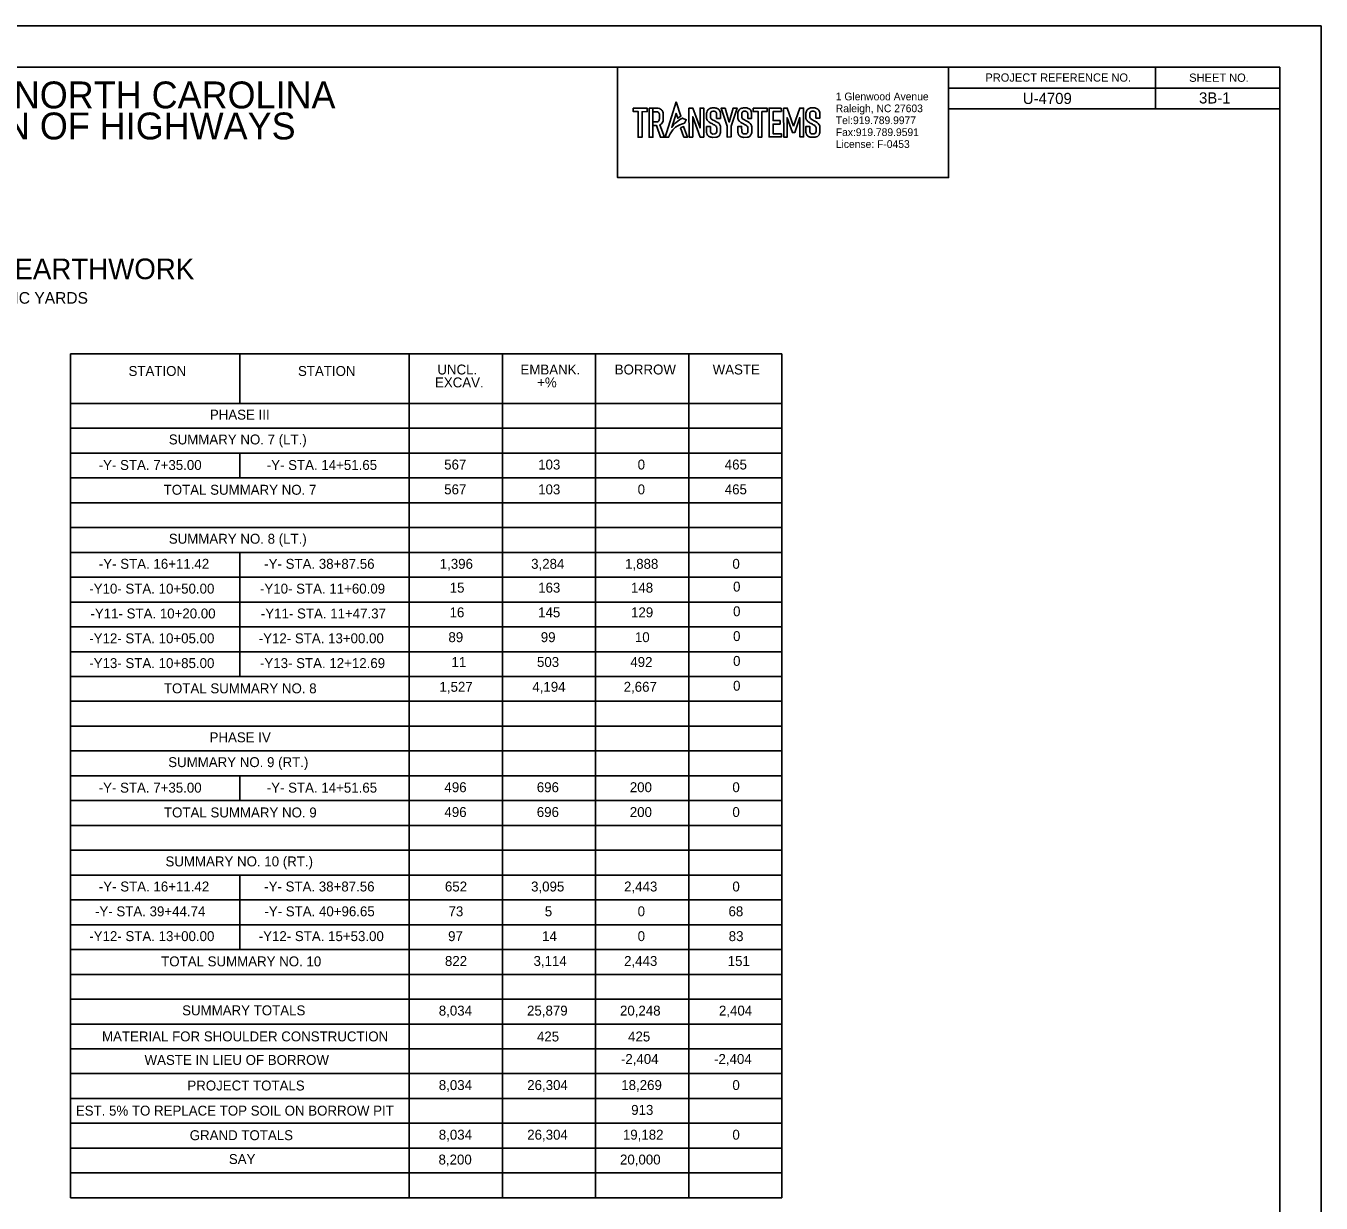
# Model space of a CAD drawing. Extents: x 573680 to 575380, y -53324 to -52224.
# Drawn here: x 574597 to 575380, y -52936 to -52224 of the extents above; entities that cross this region are included whole.
import ezdxf

# ---------------------------------------------------------------- set-up
doc = ezdxf.new("R2010")
doc.units = 0
for name, color, linetype in [('Old_Level_1', 7, 'Continuous'), ('Old_Level_2', 7, 'Continuous'), ('Old_Level_58', 7, 'Continuous'), ('Sheet Data Field CELL', 7, 'Continuous'), ('Sheet Plan And Profile CELL', 7, 'Continuous'), ('Sheet Plot Border Outside CELL', 7, 'Continuous'), ('Sheet Summary Combination CELL', 7, 'Continuous'), ('Sheet Summary Combination Grid CELL', 7, 'Continuous')]:
    doc.layers.add(name, color=color, linetype=linetype)

msp = doc.modelspace()

# ---------------------------------------------------------------- linework, layer by layer
at = {"layer": 'Old_Level_1'}
for points in [[(574990.11, -52270.23), (574983.45, -52291.56), (574985.67, -52291.55), (574986.01, -52290.71), (574986.59, -52289.55), (574986.9, -52288.92), (574987.27, -52288.39), (574987.8, -52287.63), (574988.12, -52287.16), (574988.5, -52286.77), (574988.88, -52286.37), (574989.37, -52285.88), (574989.78, -52285.61), (574990.2, -52285.27), (574990.75, -52284.95), (574991.25, -52284.67), (574992.46, -52284.1), (574993.46, -52283.69), (574995.11, -52283.13), (574996.24, -52280.99), (574994.07, -52280.04), (574992.43, -52280.92), (574991.06, -52281.83), (574990.08, -52282.62), (574989.55, -52283.05), (574989.02, -52283.62), (574988.48, -52284.18), (574988.08, -52284.61), (574987.71, -52285.26), (574987.5, -52285.62), (574990.13, -52277.24), (574991.12, -52280.13), (574993.02, -52278.87)], [(574964.15, -52274.08), (574972.62, -52274.07), (574972.62, -52276.14), (574969.51, -52276.15), (574969.52, -52291.57), (574967.17, -52291.57), (574967.16, -52276.04), (574964.19, -52276.05)], [(574973.77, -52274.08), (574976.09, -52274.08), (574976.1, -52291.64), (574973.79, -52291.65)], [(574976.09, -52276.16), (574978.48, -52276.16), (574978.78, -52276.21), (574979.18, -52276.38), (574979.5, -52276.59), (574979.74, -52276.87), (574979.89, -52277.2), (574980.01, -52277.45), (574980.01, -52278.03), (574980.02, -52280.52), (574979.96, -52280.85), (574979.88, -52281.3), (574979.75, -52281.59), (574979.55, -52281.85), (574979.28, -52282.07), (574978.85, -52282.22), (574978.53, -52282.26), (574978.2, -52282.3), (574976.09, -52282.31), (574976.1, -52284.42), (574978.21, -52284.41), (574980.58, -52291.57), (574983, -52291.55), (574980.35, -52284.01), (574980.73, -52283.87), (574981.26, -52283.47), (574981.75, -52282.94), (574982.1, -52282.31), (574982.31, -52281.67), (574982.3, -52281.49), (574982.34, -52276.92), (574982.14, -52276.18), (574981.77, -52275.5), (574981.36, -52275.03), (574980.66, -52274.55), (574979.99, -52274.33), (574979.31, -52274.1), (574978.9, -52274.1), (574976.09, -52274.08)], [(574997.88, -52274.04), (574997.9, -52291.5), (575000.13, -52291.5), (575000.12, -52279.22), (575004.58, -52291.53), (575006.83, -52291.5), (575006.8, -52273.99), (575004.63, -52274), (575004.64, -52285.98), (575000.24, -52274.04)], [(575014.58, -52280.22), (575016.89, -52280.21), (575016.89, -52276.74), (575016.69, -52276.03), (575016.41, -52275.44), (575016.11, -52275.05), (575015.74, -52274.7), (575015.3, -52274.42), (575014.88, -52274.24), (575014.88, -52274.24), (575014.42, -52274.05), (575013.94, -52273.93), (575013.62, -52273.85), (575011.87, -52273.88), (575011.34, -52273.97), (575010.88, -52274.05), (575010.42, -52274.29), (575010.01, -52274.5), (575009.62, -52274.79), (575009.31, -52275.1), (575009.07, -52275.47), (575008.87, -52275.86), (575008.62, -52276.56), (575008.57, -52277.07), (575008.57, -52280.24), (575008.68, -52280.72), (575008.91, -52281.21), (575009.2, -52281.62), (575009.5, -52281.93), (575009.95, -52282.28), (575010.4, -52282.63), (575010.69, -52282.85), (575011.17, -52283.07), (575011.65, -52283.3), (575012.04, -52283.55), (575012.48, -52283.84), (575013.01, -52284.11), (575013.44, -52284.32), (575013.87, -52284.64), (575014.18, -52284.93), (575014.43, -52285.17), (575014.59, -52285.65), (575014.68, -52285.95), (575014.65, -52288.19), (575014.49, -52288.67), (575014.24, -52289.09), (575013.91, -52289.38), (575013.56, -52289.54), (575013.22, -52289.62), (575012.25, -52289.64), (575011.93, -52289.55), (575011.6, -52289.35), (575011.27, -52289.16), (575011.13, -52288.82), (575010.99, -52288.49), (575010.88, -52288.22), (575010.84, -52285.11), (575008.5, -52285.14), (575008.55, -52288.85), (575008.66, -52289.13), (575008.93, -52289.99), (575009.11, -52290.28), (575009.36, -52290.6), (575009.74, -52290.98), (575010.05, -52291.17), (575010.48, -52291.35), (575010.64, -52291.42), (575011.07, -52291.6), (575011.6, -52291.65), (575012, -52291.69), (575014.14, -52291.64), (575014.73, -52291.5), (575015.56, -52291.12), (575015.84, -52291), (575016.46, -52290.21), (575016.79, -52289.42), (575016.95, -52288.71), (575016.9, -52285.29), (575016.89, -52284.81), (575016.76, -52284.44), (575016.57, -52284.08), (575016.03, -52283.33), (575015.32, -52282.77), (575014.34, -52282.19), (575013.6, -52281.75), (575012.14, -52280.98), (575011.38, -52280.42), (575011.05, -52280), (575010.98, -52279.71), (575010.9, -52279.43), (575010.94, -52277), (575011.07, -52276.74), (575011.19, -52276.49), (575011.37, -52276.33), (575011.6, -52276.14), (575011.86, -52276.03), (575012.12, -52275.92), (575012.27, -52275.95), (575012.28, -52275.88), (575013.24, -52275.89), (575013.52, -52276), (575013.79, -52276.11), (575014.07, -52276.22), (575014.2, -52276.42), (575014.39, -52276.69), (575014.48, -52276.97), (575014.57, -52277.25), (575014.56, -52277.55)], [(575019.85, -52274.03), (575017.31, -52274.04), (575020.93, -52284.92), (575020.96, -52291.46), (575023.35, -52291.45), (575023.32, -52284.96), (575026.98, -52273.99), (575024.49, -52274.06), (575022.18, -52282.4)], [(575033.45, -52280.2), (575035.76, -52280.2), (575035.76, -52276.72), (575035.56, -52276.01), (575035.28, -52275.42), (575034.98, -52275.03), (575034.61, -52274.68), (575034.17, -52274.4), (575033.75, -52274.22), (575033.75, -52274.22), (575033.29, -52274.03), (575032.81, -52273.91), (575032.49, -52273.83), (575030.74, -52273.87), (575030.21, -52273.96), (575029.75, -52274.04), (575029.29, -52274.28), (575028.89, -52274.49), (575028.49, -52274.77), (575028.18, -52275.08), (575027.94, -52275.45), (575027.74, -52275.84), (575027.49, -52276.54), (575027.44, -52277.06), (575027.44, -52280.23), (575027.56, -52280.7), (575027.78, -52281.2), (575028.07, -52281.61), (575028.37, -52281.92), (575028.82, -52282.26), (575029.27, -52282.61), (575029.56, -52282.83), (575030.04, -52283.06), (575030.52, -52283.28), (575030.91, -52283.53), (575031.36, -52283.82), (575031.88, -52284.09), (575032.32, -52284.31), (575032.75, -52284.62), (575033.06, -52284.92), (575033.31, -52285.15), (575033.46, -52285.64), (575033.55, -52285.93), (575033.52, -52288.17), (575033.36, -52288.65), (575033.11, -52289.07), (575032.78, -52289.37), (575032.43, -52289.53), (575032.09, -52289.6), (575031.13, -52289.62), (575030.8, -52289.53), (575030.48, -52289.33), (575030.15, -52289.14), (575030, -52288.81), (575029.86, -52288.47), (575029.75, -52288.2), (575029.71, -52285.09), (575027.37, -52285.12), (575027.42, -52288.83), (575027.54, -52289.11), (575027.81, -52289.97), (575027.98, -52290.27), (575028.23, -52290.58), (575028.61, -52290.96), (575028.92, -52291.15), (575029.35, -52291.33), (575029.51, -52291.4), (575029.94, -52291.58), (575030.48, -52291.64), (575030.87, -52291.67), (575033.01, -52291.62), (575033.6, -52291.48), (575034.43, -52291.11), (575034.71, -52290.98), (575035.33, -52290.19), (575035.67, -52289.4), (575035.82, -52288.69), (575035.77, -52285.27), (575035.76, -52284.8), (575035.63, -52284.42), (575035.44, -52284.07), (575034.9, -52283.31), (575034.19, -52282.75), (575033.22, -52282.17), (575032.47, -52281.73), (575031.01, -52280.96), (575030.25, -52280.4), (575029.93, -52279.98), (575029.85, -52279.69), (575029.77, -52279.41), (575029.82, -52276.98), (575029.94, -52276.72), (575030.06, -52276.47), (575030.24, -52276.32), (575030.47, -52276.12), (575030.73, -52276.01), (575030.99, -52275.91), (575031.14, -52275.94), (575031.15, -52275.86), (575032.11, -52275.88), (575032.39, -52275.99), (575032.67, -52276.1), (575032.94, -52276.21), (575033.07, -52276.4), (575033.26, -52276.68), (575033.35, -52276.95), (575033.44, -52277.23), (575033.44, -52277.53)], [(575036.61, -52274.01), (575045.08, -52274), (575045.08, -52276.08), (575041.97, -52276.08), (575041.98, -52291.5), (575039.63, -52291.5), (575039.62, -52275.98), (575036.65, -52275.98)], [(575053.68, -52274), (575046.3, -52274.01), (575046.31, -52291.44), (575053.78, -52291.43), (575053.78, -52289.46), (575048.74, -52289.46), (575048.73, -52283.62), (575052.95, -52283.62), (575052.95, -52281.54), (575048.69, -52281.54), (575048.69, -52276.05), (575053.7, -52276.04)], [(575061.06, -52284.85), (575057.25, -52273.93), (575055.03, -52274.04), (575055.12, -52291.5), (575057.23, -52291.49), (575057.17, -52279.81), (575060.44, -52288.8), (575061.79, -52288.83), (575064.85, -52279.7), (575064.9, -52291.42), (575067.18, -52291.41), (575067.11, -52273.99), (575064.81, -52274)], [(575074.58, -52280.16), (575076.9, -52280.16), (575076.89, -52276.68), (575076.7, -52275.98), (575076.42, -52275.39), (575076.12, -52275), (575075.75, -52274.64), (575075.31, -52274.36), (575074.88, -52274.19), (575074.88, -52274.19), (575074.42, -52273.99), (575073.94, -52273.87), (575073.62, -52273.79), (575071.87, -52273.83), (575071.34, -52273.92), (575070.88, -52274), (575070.42, -52274.24), (575070.02, -52274.45), (575069.62, -52274.73), (575069.31, -52275.05), (575069.07, -52275.41), (575068.88, -52275.81), (575068.62, -52276.5), (575068.57, -52277.02), (575068.57, -52280.19), (575068.69, -52280.66), (575068.92, -52281.16), (575069.21, -52281.57), (575069.5, -52281.88), (575069.95, -52282.23), (575070.41, -52282.57), (575070.69, -52282.79), (575071.17, -52283.02), (575071.66, -52283.24), (575072.05, -52283.5), (575072.49, -52283.78), (575073.02, -52284.05), (575073.45, -52284.27), (575073.88, -52284.58), (575074.19, -52284.88), (575074.44, -52285.12), (575074.59, -52285.6), (575074.69, -52285.9), (575074.65, -52288.13), (575074.49, -52288.62), (575074.24, -52289.04), (575073.92, -52289.33), (575073.56, -52289.49), (575073.22, -52289.56), (575072.26, -52289.58), (575071.94, -52289.49), (575071.61, -52289.3), (575071.28, -52289.1), (575071.14, -52288.77), (575070.99, -52288.43), (575070.88, -52288.17), (575070.84, -52285.05), (575068.51, -52285.08), (575068.55, -52288.79), (575068.67, -52289.07), (575068.94, -52289.93), (575069.11, -52290.23), (575069.37, -52290.55), (575069.75, -52290.92), (575070.05, -52291.11), (575070.49, -52291.3), (575070.64, -52291.36), (575071.07, -52291.54), (575071.61, -52291.6), (575072, -52291.64), (575074.14, -52291.58), (575074.74, -52291.44), (575075.56, -52291.07), (575075.84, -52290.94), (575076.46, -52290.15), (575076.8, -52289.36), (575076.95, -52288.65), (575076.9, -52285.23), (575076.89, -52284.76), (575076.76, -52284.38), (575076.57, -52284.03), (575076.03, -52283.27), (575075.32, -52282.71), (575074.35, -52282.13), (575073.6, -52281.69), (575072.14, -52280.92), (575071.39, -52280.36), (575071.06, -52279.94), (575070.98, -52279.66), (575070.9, -52279.37), (575070.95, -52276.94), (575071.07, -52276.69), (575071.2, -52276.43), (575071.37, -52276.28), (575071.61, -52276.08), (575071.86, -52275.98), (575072.12, -52275.87), (575072.27, -52275.9), (575072.29, -52275.82), (575073.24, -52275.84), (575073.52, -52275.95), (575073.8, -52276.06), (575074.08, -52276.17), (575074.21, -52276.36), (575074.39, -52276.64), (575074.48, -52276.91), (575074.58, -52277.19), (575074.57, -52277.5)], [(574992.73, -52285.93), (574994.64, -52285.17), (574996.91, -52291.61), (574994.81, -52291.53)]]:
    msp.add_lwpolyline(points, close=True, dxfattribs=at)
at = {"layer": 'Old_Level_58'}
msp.add_lwpolyline([(574954.76, -52249.31), (575154.81, -52249.31), (575154.81, -52316), (574954.76, -52316)], close=True, dxfattribs=at)
at = {"layer": 'Sheet Plan And Profile CELL'}
for points in [[(575354.86, -52249.31), (573854.86, -52249.31), (573854.86, -53299.31), (575354.86, -53299.31)], [(575154.81, -52249.31), (575354.86, -52249.31), (575354.86, -52274.36), (575154.81, -52274.36)]]:
    msp.add_lwpolyline(points, close=True, dxfattribs=at)
at = {"layer": 'Sheet Plot Border Outside CELL'}
msp.add_lwpolyline([(573679.86, -53324.31), (575379.86, -53324.31), (575379.86, -52224.31), (573679.86, -52224.31)], close=True, dxfattribs=at)
at = {"layer": 'Sheet Summary Combination CELL'}
for p, q in [((575279.86, -52249.36), (575279.86, -52274.36)), ((575154.81, -52261.86), (575354.86, -52261.86)), ((575154.81, -52274.36), (575354.86, -52274.36)), ((574773.7, -52422.43), (574773.7, -52422.43)), ((574755.34, -52422.55), (574755.34, -52422.55)), ((574762.84, -52422.67), (574762.84, -52422.67)), ((574780.42, -52422.55), (574780.42, -52422.55))]:
    msp.add_line(p, q, dxfattribs=at)
msp.add_lwpolyline([(575154.81, -52249.31), (575354.86, -52249.31), (575354.86, -52274.36), (575154.81, -52274.36)], close=True, dxfattribs=at)
at = {"layer": 'Sheet Summary Combination Grid CELL'}
for p, q in [((574624.12, -52422.49), (575054.02, -52422.49)), ((574624.12, -52422.49), (574624.12, -52932.49)), ((574726.54, -52422.49), (574726.54, -52452.49)), ((574828.9, -52422.49), (574828.9, -52662.49)), ((574885.18, -52422.49), (574885.18, -52662.49)), ((574941.46, -52422.49), (574941.46, -52662.49)), ((574997.74, -52422.49), (574997.74, -52662.49)), ((575054.02, -52422.49), (575054.02, -52932.49)), ((574624.12, -52452.49), (575054.02, -52452.49)), ((574624.12, -52467.49), (575054.02, -52467.49)), ((574624.12, -52482.49), (575054.02, -52482.49)), ((574726.54, -52482.49), (574726.54, -52497.49)), ((574624.12, -52497.49), (575054.02, -52497.49)), ((574624.12, -52512.49), (575054.02, -52512.49)), ((574624.12, -52527.49), (575054.02, -52527.49)), ((574624.12, -52542.49), (575054.02, -52542.49)), ((574726.54, -52542.49), (574726.54, -52617.49)), ((574624.12, -52557.49), (575054.02, -52557.49)), ((574624.12, -52572.49), (575054.02, -52572.49)), ((574624.12, -52587.49), (575054.02, -52587.49)), ((574624.12, -52602.49), (575054.02, -52602.49)), ((574624.12, -52617.49), (575054.02, -52617.49)), ((574624.12, -52632.49), (575054.02, -52632.49)), ((574624.12, -52647.49), (575054.02, -52647.49)), ((574624.12, -52662.49), (575054.02, -52662.49)), ((574828.9, -52662.49), (574828.9, -52932.49)), ((574885.18, -52662.49), (574885.18, -52932.49)), ((574941.46, -52662.49), (574941.46, -52932.49)), ((574997.74, -52662.49), (574997.74, -52932.49)), ((574624.12, -52677.49), (575054.02, -52677.49)), ((574726.54, -52677.49), (574726.54, -52692.49)), ((574624.12, -52692.49), (575054.02, -52692.49)), ((574624.12, -52707.49), (575054.02, -52707.49)), ((574624.12, -52722.49), (575054.02, -52722.49)), ((574624.12, -52737.49), (575054.02, -52737.49)), ((574726.54, -52737.49), (574726.54, -52782.49)), ((574624.12, -52752.49), (575054.02, -52752.49)), ((574624.12, -52767.49), (575054.02, -52767.49)), ((574624.12, -52782.49), (575054.02, -52782.49)), ((574624.12, -52797.49), (575054.02, -52797.49)), ((574624.12, -52812.49), (575054.02, -52812.49)), ((574624.12, -52827.49), (575054.02, -52827.49)), ((574624.12, -52842.49), (575054.02, -52842.49)), ((574624.12, -52857.49), (575054.02, -52857.49)), ((574624.12, -52872.49), (575054.02, -52872.49)), ((574624.12, -52887.49), (575054.02, -52887.49)), ((574624.12, -52902.49), (575054.02, -52902.49)), ((574624.12, -52917.49), (575054.02, -52917.49)), ((574624.12, -52932.49), (575054.02, -52932.49))]:
    msp.add_line(p, q, dxfattribs=at)

# ---------------------------------------------------------------- texts
at = {"layer": 'Old_Level_2'}
for s, p in [('1 Glenwood Avenue', (575086.61, -52269.28)), ('Raleigh, NC 27603', (575086.61, -52276.47)), ('Tel:919.789.9977 ', (575086.61, -52283.67)), ('Fax:919.789.9591', (575086.61, -52290.87)), ('License: F-0453', (575086.61, -52298.06))]:
    msp.add_text(s, height=4.6576, rotation=360, dxfattribs=at).set_placement(p)
at = {"layer": 'Sheet Data Field CELL'}
for s, p in [('U-4709', (575199.61, -52271.51)), ('3B-1', (575306.08, -52271.21))]:
    msp.add_text(s, height=6.75, dxfattribs=at).set_placement(p)
at = {"layer": 'Sheet Plan And Profile CELL'}
for s, height, p in [('PROJECT REFERENCE NO.', 5.0001, (575177.01, -52258.01)), ('SHEET NO.', 5, (575300.16, -52258.11))]:
    msp.add_text(s, height=height, rotation=360, dxfattribs=at).set_placement(p)
at = {"layer": 'Sheet Summary Combination CELL'}
for s, height, p in [('STATE OF NORTH CAROLINA', 16.2501, (574477.61, -52274.16)), ('PROJECT REFERENCE NO.', 5.0001, (575177.01, -52258.01)), ('SHEET NO.', 5, (575300.16, -52258.11)), ('DIVISION OF HIGHWAYS', 16.2501, (574504.21, -52292.91)), ('STATION', 6, (574659.22, -52435.85)), ('STATION', 6, (574761.61, -52435.85)), ('UNCL.', 6, (574845.85, -52434.97)), ('EMBANK.', 6, (574896.06, -52434.97)), ('BORROW', 6, (574953.01, -52434.97)), ('WASTE', 6, (575012.21, -52434.97)), ('EXCAV.', 6, (574844.41, -52442.77)), ('+%', 6, (574906.14, -52442.77)), ('PHASE III', 6, (574708.38, -52462.24)), ('SUMMARY NO. 7 (LT.)', 6, (574683.55, -52477.24)), ('-Y- STA. 7+35.00', 6, (574641.18, -52492.66)), ('-Y- STA. 14+51.65', 6, (574742.75, -52492.66)), ('567', 6, (574849.96, -52492.4)), ('103', 6, (574906.76, -52492.4)), ('0', 6, (574966.87, -52492.4)), ('465', 6, (575019.51, -52492.4)), ('TOTAL SUMMARY NO. 7', 6, (574680.45, -52507.65)), ('567', 6, (574849.96, -52507.4)), ('103', 6, (574906.76, -52507.4)), ('0', 6, (574966.87, -52507.4)), ('465', 6, (575019.51, -52507.4)), ('SUMMARY NO. 8 (LT.)', 6, (574683.55, -52537.24)), ('-Y- STA. 16+11.42', 6, (574641.29, -52552.4)), ('-Y- STA. 38+87.56', 6, (574741.22, -52552.4)), ('1,396', 6, (574847.27, -52552.4)), ('3,284', 6, (574902.51, -52552.4)), ('1,888', 6, (574959.29, -52552.4)), ('0', 6, (575024.13, -52552.4)), ('-Y10- STA. 10+50.00', 6, (574635.5, -52567.4)), ('-Y10- STA. 11+60.09', 6, (574738.66, -52567.4)), ('15', 6, (574853.31, -52566.8)), ('163', 6, (574906.76, -52566.8)), ('148', 6, (574962.84, -52566.8)), ('0', 6, (575024.53, -52566.17)), ('-Y11- STA. 10+20.00', 6, (574636.22, -52582.4)), ('-Y11- STA. 11+47.37', 6, (574739.19, -52582.4)), ('16', 6, (574853.21, -52581.72)), ('145', 6, (574906.74, -52581.72)), ('129', 6, (574962.89, -52581.72)), ('0', 6, (575024.53, -52581.08)), ('-Y12- STA. 10+05.00', 6, (574635.5, -52597.4)), ('-Y12- STA. 13+00.00', 6, (574737.89, -52597.4)), ('89', 6, (574852.52, -52596.72)), ('99', 6, (574908.33, -52596.72)), ('10', 6, (574965.21, -52596.72)), ('0', 6, (575024.53, -52596.08)), ('-Y13- STA. 10+85.00', 6, (574635.5, -52612.4)), ('-Y13- STA. 12+12.69', 6, (574738.66, -52612.4)), ('11', 6, (574854.37, -52611.72)), ('503', 6, (574906.04, -52611.72)), ('492', 6, (574962.45, -52611.72)), ('0', 6, (575024.53, -52611.08)), ('TOTAL SUMMARY NO. 8', 6, (574680.59, -52627.65)), ('1,527', 6, (574847.12, -52626.72)), ('4,194', 6, (574903.23, -52626.72)), ('2,667', 6, (574958.42, -52626.72)), ('0', 6, (575024.53, -52626.08)), ('PHASE IV', 6, (574708.19, -52657.24)), ('SUMMARY NO. 9 (RT.)', 6, (574683.2, -52672.24)), ('-Y- STA. 7+35.00', 6, (574641.18, -52687.66)), ('-Y- STA. 14+51.65', 6, (574742.75, -52687.66)), ('496', 6, (574850.12, -52687.4)), ('696', 6, (574905.92, -52687.4)), ('200', 6, (574962.12, -52687.4)), ('0', 6, (575024.13, -52687.4)), ('496', 6, (574850.12, -52702.4)), ('696', 6, (574905.92, -52702.4)), ('200', 6, (574962.12, -52702.4)), ('0', 6, (575024.13, -52702.4)), ('TOTAL SUMMARY NO. 9', 6, (574680.64, -52702.65)), ('SUMMARY NO. 10 (RT.)', 6, (574681.54, -52732.24)), ('-Y- STA. 16+11.42', 6, (574641.29, -52747.4)), ('-Y- STA. 38+87.56', 6, (574741.22, -52747.4)), ('652', 6, (574850.42, -52747.4)), ('3,095', 6, (574902.47, -52747.4)), ('2,443', 6, (574958.69, -52747.4)), ('0', 6, (575024.13, -52747.4)), ('-Y- STA. 39+44.74', 6, (574638.97, -52762.4)), ('-Y- STA. 40+96.65', 6, (574741.32, -52762.4)), ('73', 6, (574852.6, -52762.4)), ('5', 6, (574910.77, -52762.4)), ('0', 6, (574966.87, -52762.4)), ('68', 6, (575021.77, -52762.4)), ('-Y12- STA. 13+00.00', 6, (574635.5, -52777.4)), ('-Y12- STA. 15+53.00', 6, (574737.89, -52777.4)), ('97', 6, (574852.33, -52777.4)), ('14', 6, (574909.16, -52777.4)), ('0', 6, (574966.87, -52777.4)), ('83', 6, (575021.89, -52777.4)), ('TOTAL SUMMARY NO. 10', 6, (574678.93, -52792.65)), ('822', 6, (574850.42, -52792.4)), ('3,114', 6, (574903.95, -52792.4)), ('2,443', 6, (574958.69, -52792.4)), ('151', 6, (575021.29, -52792.4)), ('SUMMARY TOTALS', 6, (574691.62, -52822.24)), ('8,034', 6, (574846.7, -52822.4)), ('25,879', 6, (574900.02, -52822.4)), ('20,248', 6, (574956.19, -52822.4)), ('2,404', 6, (575015.99, -52822.4)), ('MATERIAL FOR SHOULDER CONSTRUCTION', 6, (574643.18, -52837.99)), ('425', 6, (574906.03, -52838.04)), ('425', 6, (574961.09, -52838.04)), ('WASTE IN LIEU OF BORROW', 6, (574668.9, -52852.22)), ('-2,404', 6, (574956.76, -52851.63)), ('-2,404', 6, (575013.04, -52851.63)), ('PROJECT TOTALS', 6, (574694.79, -52867.67)), ('8,034', 6, (574846.7, -52867.4)), ('26,304', 6, (574900.14, -52867.4)), ('18,269', 6, (574956.96, -52867.4)), ('0', 6, (575024.13, -52867.4)), ('913', 6, (574962.97, -52882.4)), ('EST. 5% TO REPLACE TOP SOIL ON BORROW PIT', 6, (574627.38, -52882.85)), ('GRAND TOTALS', 6, (574696.2, -52897.69)), ('8,034', 6, (574846.7, -52897.4)), ('26,304', 6, (574900.14, -52897.4)), ('19,182', 6, (574957.95, -52897.4)), ('0', 6, (575024.13, -52897.4)), ('SAY', 6, (574719.84, -52912.11)), ('8,200', 6, (574846.54, -52912.4)), ('20,000', 6, (574956.19, -52912.4))]:
    msp.add_text(s, height=height, dxfattribs=at).set_placement(p)
for s, height, p in [('SUMMARY OF EARTHWORK', 12.5001, (574472.34, -52377.44)), ('IN CUBIC YARDS', 7.0313, (574558.43, -52392.21))]:
    msp.add_text(s, height=height, rotation=0.01193, dxfattribs=at).set_placement(p)

doc.saveas('drawing.dxf')
